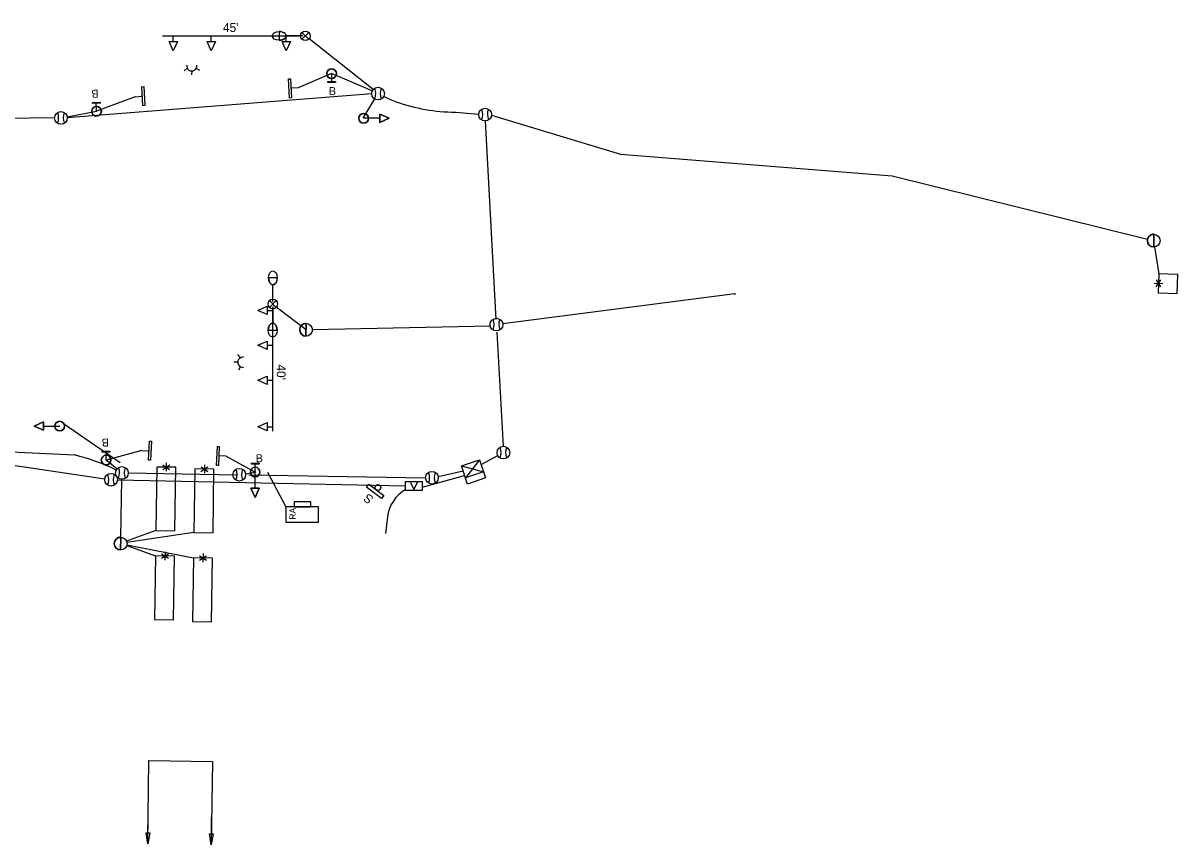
# Model space of a CAD drawing. Extents: x 596176 to 605330, y 332416 to 402398.
# Drawn here: x 602923.8 to 603287.5, y 365951.4 to 366210 of the extents above; entities that cross this region are included whole.
import ezdxf

# ---------------------------------------------------------------- set-up
doc = ezdxf.new("R2010")
doc.units = 0
for name, color, linetype in [('P_LTG', 7, 'Continuous'), ('P_SIG', 7, 'Continuous'), ('P_SIG_Bold', 7, 'Continuous'), ('P_SIG_Conduit', 7, 'Continuous'), ('P_SIG_IC', 7, 'Continuous'), ('P_SIG_Loops', 7, 'Continuous')]:
    doc.layers.add(name, color=color, linetype=linetype)

# ---------------------------------------------------------------- blocks, each defined once
blk = doc.blocks.new('_U303')
at = {"layer": 'P_LTG'}
for p, q in [((4.3, 25.1), (-4.1, 25.1)), ((0, 2.3), (0, 18.4))]:
    blk.add_line(p, q, dxfattribs=at)
blk.add_ellipse((0.1, 25.1), major_axis=(0, 6.65), ratio=0.636439, dxfattribs=at)
blk.add_ellipse((0.1, 25.1), major_axis=(0, 6.65), ratio=0.636439, start_param=1.570796, end_param=4.712389, dxfattribs=at)
blk = doc.blocks.new('_U312')
at = {"layer": 'P_SIG_Loops'}
for p, q in [((0.1, -0.1), (-0.1, 0.1)), ((-0.1, -0.1), (0.1, 0.1)), ((0, 0), (0, -0.2)), ((-0.1, 0), (0.1, 0))]:
    blk.add_line(p, q, dxfattribs=at)
blk.add_lwpolyline([(0, -0.2), (0.5, -0.2), (0.5, 0.2), (0, 0.2)], close=True, dxfattribs=at)

msp = doc.modelspace()

# ---------------------------------------------------------------- linework, layer by layer
at = {"layer": 'P_SIG'}
for p, q in [((602971.03, 366204.25), (602971.03, 366206.02)), ((602983.03, 366204.25), (602983.03, 366206.02)), ((603006.65, 366204.25), (603006.65, 366206.02)), ((602975.45, 366195.87), (602974.45, 366195.01)), ((602976.85, 366195), (602976.83, 366193.77)), ((602978.24, 366195.8), (602979.31, 366195.19)), ((603020.92, 366194.15), (603010.37, 366189.66)), ((603020.92, 366194.15), (603020.92, 366191.65)), ((602959.04, 366186.88), (602946.88, 366182.29)), ((602959.04, 366186.88), (602961.44, 366187)), ((603010.37, 366189.66), (603007.97, 366189.54)), ((602946.88, 366182.29), (602946.79, 366184.79)), ((603036.07, 366180.08), (603031.01, 366180.09)), ((603279.92, 366143.61), (603279.89, 366139.61)), ((603000.64, 366119.64), (603002.41, 366119.64)), ((603012.88, 366115.51), (603012.86, 366111.51)), ((603000.64, 366108.64), (603002.41, 366108.64)), ((602991.39, 366103.3), (602990.16, 366103.3)), ((602992.24, 366104.71), (602991.36, 366105.7)), ((602992.21, 366101.92), (602991.61, 366100.85)), ((603000.64, 366097.64), (603002.41, 366097.64)), ((602930.22, 366083.21), (602935.28, 366083.2)), ((603000.64, 366083.01), (603002.41, 366083.01)), ((602961.17, 366075.58), (602949.91, 366072.51)), ((602949.91, 366072.51), (602949.91, 366075.01)), ((602961.17, 366075.58), (602963.57, 366075.46)), ((602987.67, 366073.74), (602985.27, 366073.86)), ((602987.67, 366073.74), (602996.83, 366068.75)), ((602996.85, 366068.75), (602996.89, 366071.25)), ((603061.82, 366070.67), (603067.51, 366072.58)), ((603061.82, 366070.67), (603067.51, 366072.58)), ((603063.74, 366064.98), (603061.82, 366070.67)), ((603061.82, 366070.67), (603068.78, 366068.79)), ((603063.74, 366064.98), (603061.82, 366070.67)), ((603061.82, 366070.67), (603068.78, 366068.79)), ((603067.51, 366072.58), (603063.1, 366066.88)), ((603067.51, 366072.58), (603063.1, 366066.88)), ((603067.51, 366072.58), (603069.42, 366066.9)), ((603067.51, 366072.58), (603069.42, 366066.9)), ((602996.84, 366063.67), (602996.85, 366068.73)), ((603000.76, 366068.75), (603006.46, 366057.78)), ((603068.78, 366068.79), (603063.1, 366066.88)), ((603068.78, 366068.79), (603063.1, 366066.88)), ((603069.42, 366066.9), (603063.74, 366064.98)), ((603069.42, 366066.9), (603063.74, 366064.98)), ((603031.87, 366064.02), (603032.6, 366064.97)), ((603036.65, 366060.38), (603031.87, 366064.02)), ((603032.6, 366064.97), (603037.37, 366061.34)), ((603045.78, 366065.45), (603046.82, 366063.28)), ((603047.86, 366065.45), (603046.82, 366063.28)), ((603037.37, 366061.34), (603036.65, 366060.38)), ((602954.5, 366048.25), (602954.48, 366044.25))]:
    msp.add_line(p, q, dxfattribs=at)
for points in [[(602971.03, 366201.3), (602969.71, 366204.25), (602972.34, 366204.25)], [(602983.03, 366201.3), (602981.71, 366204.25), (602984.35, 366204.25)], [(603006.65, 366201.3), (603005.34, 366204.25), (603007.97, 366204.25)], [(602961.46, 366184.04), (602961.15, 366190.03), (602961.75, 366190.06), (602962.06, 366184.07)], [(603007.95, 366192.5), (603008.26, 366186.5), (603007.66, 366186.47), (603007.35, 366192.47)], [(603019.72, 366191.65), (603022.12, 366191.65), (603022.12, 366191.33), (603019.72, 366191.33)], [(602947.99, 366184.83), (602945.6, 366184.74), (602945.58, 366185.07), (602947.98, 366185.16)], [(602997.68, 366119.64), (603000.64, 366120.96), (603000.64, 366118.32)], [(602997.68, 366108.64), (603000.64, 366109.96), (603000.64, 366107.32)], [(602997.68, 366097.64), (603000.64, 366098.96), (603000.64, 366096.32)], [(602997.68, 366083.01), (603000.64, 366084.33), (603000.64, 366081.69)], [(602963.28, 366072.51), (602963.59, 366078.51), (602964.19, 366078.47), (602963.88, 366072.48)], [(602951.11, 366075.01), (602948.71, 366075.01), (602948.71, 366075.34), (602951.11, 366075.34)], [(602985.56, 366076.81), (602985.25, 366070.82), (602984.65, 366070.85), (602984.96, 366076.84)], [(602998.09, 366071.23), (602995.69, 366071.26), (602995.69, 366071.59), (602998.09, 366071.56)], [(603037.37, 366061.34), (603036.65, 366060.38), (603031.87, 366064.02), (603032.6, 366064.97)], [(603044.23, 366065.82), (603049.45, 366065.82), (603049.45, 366062.91), (603044.23, 366062.91)], [(603009.09, 366059.42), (603009.09, 366057.82), (603014.36, 366057.82), (603014.36, 366059.42)], [(603016.81, 366057.78), (603006.46, 366057.78), (603006.46, 366052.96), (603016.81, 366052.96)]]:
    msp.add_lwpolyline(points, close=True, dxfattribs=at)
for points in [[(603039.03, 366180.08), (603036.07, 366178.76), (603036.07, 366181.4), (603039.03, 366180.08)], [(603036.07, 366178.76), (603039.03, 366180.08), (603036.07, 366181.4), (603036.07, 366178.76)], [(603279.89, 366139.61), (603279.92, 366143.61)], [(603012.86, 366111.51), (603012.88, 366115.51)], [(602927.26, 366083.21), (602930.22, 366084.53), (602930.22, 366081.89), (602927.26, 366083.21)], [(602930.22, 366084.53), (602927.26, 366083.21), (602930.22, 366081.89), (602930.22, 366084.53)], [(602996.84, 366060.71), (602995.53, 366063.67), (602998.16, 366063.67), (602996.84, 366060.71)], [(602995.53, 366063.67), (602996.84, 366060.71), (602998.16, 366063.67), (602995.53, 366063.67)], [(602954.48, 366044.25), (602954.5, 366048.25)]]:
    msp.add_lwpolyline(points, dxfattribs=at)
for centre, radius in [((603020.92, 366194.15), 1.52), ((603035.56, 366187.87), 2), ((602946.88, 366182.29), 1.52), ((603069.29, 366181.26), 2), ((602935.66, 366180.21), 2), ((603031.01, 366180.09), 1.52), ((603031.01, 366180.09), 1.52), ((603031.01, 366180.09), 1.52), ((603279.9, 366141.61), 2), ((603072.86, 366115.17), 2), ((603012.87, 366113.51), 2), ((602935.28, 366083.2), 1.52), ((602935.28, 366083.2), 1.52), ((602935.28, 366083.2), 1.52), ((602949.91, 366072.51), 1.52), ((603075.04, 366074.89), 2), ((602954.86, 366068.49), 2), ((602991.84, 366067.9), 2), ((602996.85, 366068.73), 1.52), ((602996.85, 366068.73), 1.52), ((602996.85, 366068.73), 1.52), ((602951.45, 366066.31), 2), ((603052.52, 366066.94), 2), ((603035.52, 366063.88), 0.9), ((602954.49, 366046.25), 2)]:
    msp.add_circle(centre, radius, dxfattribs=at)
for centre, radius, start, end in [((602976.87, 366196.58), 1.58, 171.3381, 6.8456), ((603020.92, 366194.15), 1.52, 0, 180), ((603020.92, 366194.15), 1.52, 180, 0), ((603030.49, 366187.91), 4.36, 336.6741, 22.5272), ((603040.63, 366187.92), 4.36, 157.5751, 203.4282), ((602946.88, 366182.29), 1.52, 169.6441, 349.6441), ((602946.88, 366182.29), 1.52, 349.6441, 169.6441), ((603064.22, 366181.29), 4.36, 336.6741, 22.5272), ((603074.36, 366181.3), 4.36, 157.5751, 203.4282), ((602930.59, 366180.25), 4.36, 336.6741, 22.5272), ((602940.73, 366180.25), 4.36, 157.5751, 203.4282), ((603031.01, 366180.09), 1.52, 0, 180), ((603031.01, 366180.09), 1.52, 180, 0), ((603279.9, 366141.61), 2, 89.7008, 180), ((603279.9, 366141.61), 2, 180, 269.7008), ((603012.87, 366113.51), 2, 89.7008, 180), ((603012.87, 366113.51), 2, 180, 269.7008), ((603067.79, 366115.2), 4.36, 336.6741, 22.5272), ((603077.93, 366115.21), 4.36, 157.5751, 203.4282), ((602992.96, 366103.31), 1.58, 82.2462, 277.7538), ((602935.28, 366083.2), 1.52, 0, 180), ((602935.28, 366083.2), 1.52, 180, 0), ((602949.91, 366072.51), 1.52, 90, 270), ((602949.91, 366072.51), 1.52, 270, 90), ((603069.97, 366074.92), 4.36, 336.6741, 22.5272), ((603080.11, 366074.93), 4.36, 157.5751, 203.4282), ((602949.79, 366068.53), 4.36, 336.6741, 22.5272), ((602959.93, 366068.53), 4.36, 157.5751, 203.4282), ((602996.85, 366068.73), 1.52, 90, 270), ((602996.85, 366068.73), 1.52, 270, 90), ((602946.38, 366066.35), 4.36, 336.6741, 22.5272), ((602956.52, 366066.36), 4.36, 157.5751, 203.4282), ((602986.77, 366067.94), 4.36, 336.6741, 22.5272), ((602996.91, 366067.95), 4.36, 157.5751, 203.4282), ((603047.45, 366066.98), 4.36, 336.6741, 22.5272), ((603057.59, 366066.99), 4.36, 157.5751, 203.4282), ((602954.49, 366046.25), 2, 89.7008, 180), ((602954.49, 366046.25), 2, 180, 269.7008)]:
    msp.add_arc(centre, radius, start, end, dxfattribs=at)
at = {"layer": 'P_SIG_Bold'}
for p, q in [((602967.65, 366206.02), (603011.15, 366206.02)), ((603011.59, 366207.09), (603013.72, 366204.96)), ((603013.72, 366207.09), (603011.59, 366204.96)), ((603001.35, 366120.58), (603003.47, 366122.7)), ((603001.35, 366122.7), (603003.47, 366120.58)), ((603002.41, 366081.64), (603002.41, 366120.14))]:
    msp.add_line(p, q, dxfattribs=at)
for centre in [(603012.65, 366206.02), (603002.41, 366121.64)]:
    msp.add_circle(centre, 1.5, dxfattribs=at)
at = {"layer": 'P_SIG_Conduit'}
msp.add_line((603033.74, 366188.71), (603020.92, 366194.15), dxfattribs=at)
for points in [[(603034.02, 366189.15), (603013.83, 366205.09)], [(603033.56, 366187.73), (602937.66, 366180.18)], [(603030.89, 366180.16), (603034.5, 366186.16)], [(602933.66, 366180.19), (602901.53, 366179.86)], [(602937.63, 366180.57), (602946.88, 366182.29)], [(603059.93, 366182.01), (603067.3, 366181.42)], [(603072.78, 366116.74), (603069.4, 366179.26)], [(603071.29, 366181.1), (603111.89, 366168.83), (603197.51, 366161.96), (603277.96, 366142.08), (603277.96, 366142.08), (603277.96, 366142.08)], [(603147.9, 366124.83), (603074.85, 366115.38)], [(603012.87, 366113.5), (603003.5, 366120.6)], [(603070.89, 366114.64), (603014.87, 366113.56)], [(603072.99, 366112.75), (603074.93, 366076.88)], [(602954.29, 366071.62), (602936.49, 366083.88)], [(602899.9, 366076.04), (602939.94, 366074.13)], [(603067.99, 366071.15), (603073.27, 366073.95)], [(602953.32, 366069.73), (602949.91, 366072.51)], [(602954.52, 366048.25), (602954.81, 366066.49)], [(602956.86, 366068.46), (602990.84, 366067.92)], [(602993.81, 366068.23), (602996.85, 366068.75)], [(602994.84, 366067.85), (603050.52, 366066.97)], [(603054.47, 366067.37), (603062.36, 366069.09)]]:
    msp.add_lwpolyline(points, dxfattribs=at)
for centre, radius, start, end in [((603057.39, 366228.36), 46, 244.1508, 249.4009), ((603060.45, 366239.9), 57.9, 250.585, 269.4867), ((602924.71, 366011.34), 64.61, 63.9564, 76.3669)]:
    msp.add_arc(centre, radius, start, end, dxfattribs=at)
at = {"layer": 'P_SIG_IC'}
for points in [[(602759.42, 366075.93), (602894.42, 366074.85), (602949.47, 366066.61)], [(602953.45, 366066.27), (603044.23, 366064.42)], [(603049.45, 366064.03), (603062.82, 366067.7)], [(603038.53, 366054.67), (603037.9, 366049.4)]]:
    msp.add_lwpolyline(points, dxfattribs=at)
msp.add_arc((603050.02, 366053.23), 11.58, 119.998, 172.8835, dxfattribs=at)
at = {"layer": 'P_SIG_Loops'}
for p, q in [((603280.1, 366139.62), (603281.49, 366131.17)), ((603280.02, 366128.2), (603282.7, 366128.11)), ((603280.64, 366127.09), (603282.11, 366129.22)), ((603282.09, 366127.06), (603280.73, 366129.27)), ((603281.39, 366128.17), (603281.29, 366125.17)), ((602968.86, 366070.29), (602965.86, 366070.33)), ((602967.75, 366069.57), (602969.95, 366070.97)), ((602967.76, 366071.03), (602969.91, 366069.58)), ((602968.86, 366071.66), (602968.82, 366068.98)), ((602979.78, 366068.95), (602981.98, 366070.34)), ((602979.79, 366070.4), (602981.94, 366068.96)), ((602980.89, 366071.04), (602980.85, 366068.36)), ((602980.88, 366069.66), (602977.89, 366069.71)), ((602965.54, 366050.34), (602956.34, 366047.01)), ((602977.57, 366049.71), (602956.46, 366046.58)), ((602956.4, 366045.64), (602965.41, 366042.34)), ((602956.46, 366045.89), (602977.44, 366041.71)), ((602968.45, 366042.32), (602965.45, 366042.36)), ((602967.35, 366041.6), (602969.54, 366043)), ((602967.36, 366043.05), (602969.51, 366041.61)), ((602968.45, 366043.69), (602968.41, 366041.01)), ((602980.44, 366041.69), (602977.44, 366041.74)), ((602979.34, 366040.98), (602981.53, 366042.37)), ((602979.35, 366042.43), (602981.5, 366040.99)), ((602980.45, 366043.07), (602980.4, 366040.39))]:
    msp.add_line(p, q, dxfattribs=at)
for points in [[(603281.29, 366125.17), (603287.29, 366124.98), (603287.49, 366130.97), (603281.49, 366131.17)], [(602965.86, 366070.33), (602965.54, 366050.34), (602971.54, 366050.24), (602971.86, 366070.24)], [(602977.89, 366069.71), (602977.57, 366049.71), (602983.57, 366049.62), (602983.88, 366069.62)], [(602965.45, 366042.36), (602965.13, 366022.36), (602971.13, 366022.27), (602971.45, 366042.27)], [(602977.44, 366041.74), (602977.12, 366021.74), (602983.12, 366021.65), (602983.44, 366041.64)], [(602963.63, 365955.22), (602963, 365951.73), (602962.47, 365955.24)], [(602983.63, 365954.9), (602982.99, 365951.41), (602982.47, 365954.92)]]:
    msp.add_lwpolyline(points, close=True, dxfattribs=at)
for points in [[(602963, 365951.73), (602963.41, 365977.92), (602983.41, 365977.61), (602982.99, 365951.41)], [(602963.05, 365955.23), (602963.13, 365960.3)], [(602983.05, 365954.91), (602983.13, 365959.98)]]:
    msp.add_lwpolyline(points, dxfattribs=at)

# ---------------------------------------------------------------- block references
at = {"layer": 'P_LTG'}
for name, p, xscale, yscale, rotation in [('_U303', (603012.64, 366206.02), 0.3280833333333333, 0.3280833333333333, 90.21206877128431), ('_U312', (603147.9, 366124.83), 0.32808333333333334, 0.3280833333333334, -4.411604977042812), ('_U303', (603002.41, 366121.64), 0.32808333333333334, 0.32808333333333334, 180), ('_U312', (602996.85, 366068.75), 0.32808333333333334, 0.32808333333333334, 90)]:
    msp.add_blockref(name, p, dxfattribs=dict(at, xscale=xscale, yscale=yscale, rotation=rotation))
at = {"layer": 'P_LTG', "xscale": 0.32808333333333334, "yscale": 0.32808333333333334}
msp.add_blockref('_U303', (603002.41, 366121.64), dxfattribs=at)

# ---------------------------------------------------------------- texts
at = {"layer": 'P_SIG'}
for s, height, rotation, p in [('B', 2.52, 360, (603020.08, 366187.38)), ('B', 2.52, 182.0685, (602947.48, 366189.09)), ('B', 2.52, 180, (602950.75, 366079.28)), ('B', 2.52, 360, (602997.03, 366071.83)), ('S', 2.8, 142.706, (603034.36, 366060.68)), ('RA', 2, 90, (603009.65, 366053.78))]:
    msp.add_text(s, height=height, rotation=rotation, dxfattribs=at).set_placement(p)
at = {"layer": 'P_SIG_Bold'}
msp.add_text("45'", height=2.8, dxfattribs=at).set_placement((602986.7, 366207.24))
msp.add_text("40'", height=2.8, rotation=270, dxfattribs=at).set_placement((603003.63, 366102.62))

doc.saveas('drawing.dxf')
